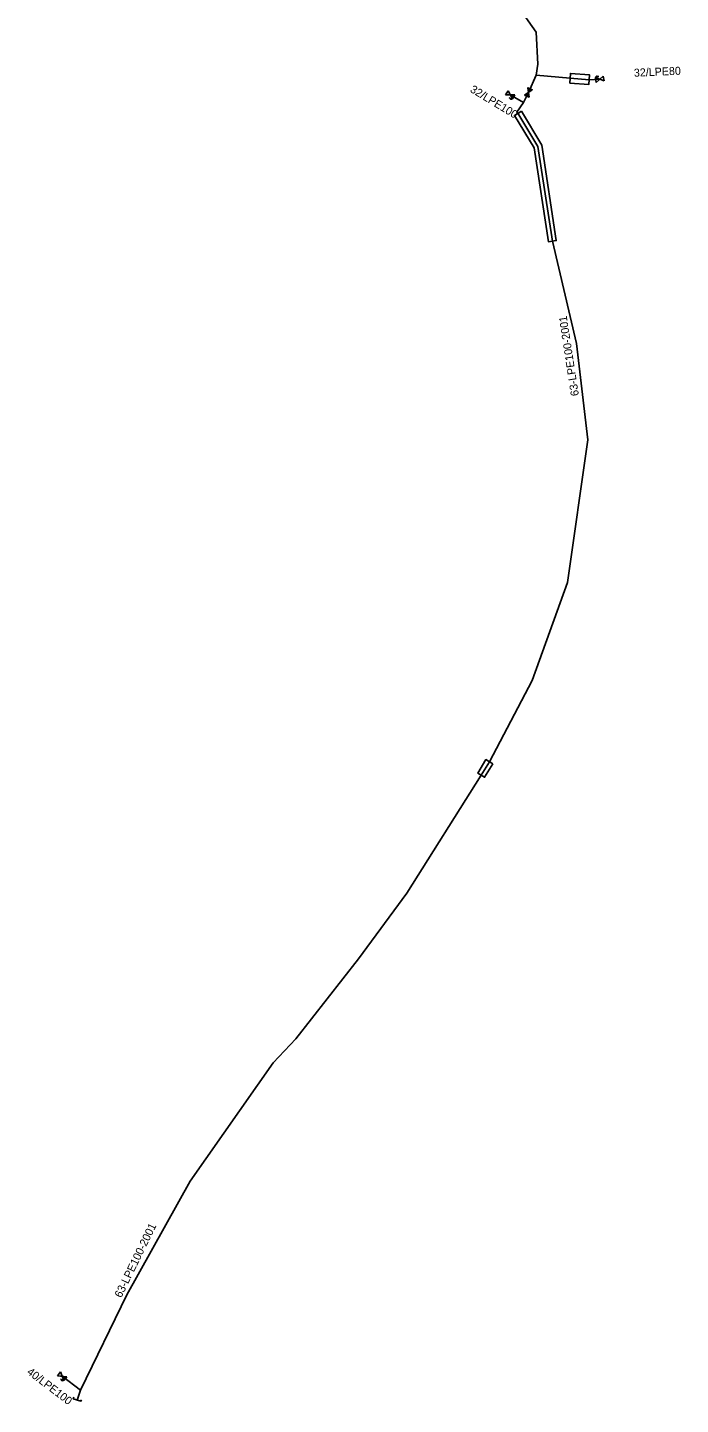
# Model space of a CAD drawing. Extents: x -787723 to -786204, y -1153846 to -1152384.
# Drawn here: x -786628.8 to -786547.2, y -1153807.1 to -1153635 of the extents above; entities that cross this region are included whole.
import ezdxf

# ---------------------------------------------------------------- set-up
doc = ezdxf.new("R2010")
doc.units = 0
for name, color, linetype in [('Vrstva 1', 7, 'Continuous'), ('Vrstva 21', 7, 'Continuous'), ('Vrstva 22', 7, 'Continuous'), ('Vrstva 29', 7, 'Continuous'), ('Vrstva 31', 7, 'Continuous'), ('Vrstva 32', 7, 'Continuous')]:
    doc.layers.add(name, color=color, linetype=linetype)

# ---------------------------------------------------------------- blocks, each defined once
blk = doc.blocks.new('DEC063-SN')
at = {"layer": 'Vrstva 1'}
for p, q in [((-0.5, -0.3), (0.5, 0.3)), ((0.5, -0.3), (-0.5, 0.3)), ((-0.5, 0.3), (-0.5, -0.3)), ((0.5, 0.3), (0.5, -0.3)), ((0.126, -0.318), (0.126, -0.458)), ((0.126, -0.384), (0.206, -0.384)), ((0.206, -0.458), (0.206, -0.318)), ((0.366, -0.458), (0.366, -0.318))]:
    blk.add_line(p, q, dxfattribs=at)
for points in [[(0.246, -0.318), (0.246, -0.418), (0.252, -0.438), (0.264, -0.451), (0.281, -0.458), (0.292, -0.458), (0.309, -0.451), (0.321, -0.438), (0.326, -0.418), (0.326, -0.318)], [(0.366, -0.318), (0.418, -0.318), (0.435, -0.325), (0.441, -0.331), (0.446, -0.344), (0.446, -0.364), (0.441, -0.378), (0.435, -0.384), (0.418, -0.391), (0.366, -0.391)]]:
    blk.add_lwpolyline(points, dxfattribs=at)
blk = doc.blocks.new('DEC130')
at = {"layer": 'Vrstva 1'}
blk.add_lwpolyline([(0.2, 0.5), (0, 0.5), (0, -0.5), (0.2, -0.5)], dxfattribs=at)
blk = doc.blocks.new('DEC124')
at = {"layer": 'Vrstva 1'}
blk.add_lwpolyline([(-0.5, 0.3), (0.5, -0.3), (0.5, 0.3), (-0.5, -0.3), (-0.5, 0.3)], dxfattribs=at)

msp = doc.modelspace()

# ---------------------------------------------------------------- linework, layer by layer
at = {"layer": 'Vrstva 21'}
for points in [[(-786567.51, -1153632.31), (-786565.2, -1153635.57), (-786565, -1153639.57), (-786565.22, -1153640.95), (-786566.18, -1153643.1)], [(-786566.18, -1153643.1), (-786566.79, -1153644.36), (-786567.65, -1153645.57), (-786567.5, -1153645.71), (-786565.01, -1153649.85), (-786563.19, -1153661.69), (-786560.19, -1153674.46), (-786558.76, -1153686.53), (-786561.3, -1153704.35), (-786565.7, -1153716.59), (-786571.07, -1153726.74), (-786572.1, -1153728.42), (-786581.4, -1153743.15), (-786587.43, -1153751.39), (-786595.25, -1153761.37), (-786598.11, -1153764.36), (-786608.48, -1153779.17), (-786616.39, -1153793.35), (-786622.2, -1153805.28), (-786622.61, -1153806.5)]]:
    msp.add_lwpolyline(points, dxfattribs=at)
at = {"layer": 'Vrstva 29'}
for points in [[(-786561.03, -1153641.93), (-786560.93, -1153640.73), (-786558.54, -1153640.92), (-786558.64, -1153642.12)], [(-786567.07, -1153645.45), (-786564.53, -1153649.68), (-786562.7, -1153661.61), (-786563.68, -1153661.77), (-786565.49, -1153650.02), (-786567.93, -1153645.97)], [(-786570.64, -1153727), (-786571.67, -1153728.68), (-786572.53, -1153728.16), (-786571.5, -1153726.48)]]:
    msp.add_lwpolyline(points, close=True, dxfattribs=at)
at = {"layer": 'Vrstva 31'}
for points in [[(-786565.22, -1153640.95), (-786560.98, -1153641.33), (-786558.59, -1153641.52), (-786557.27, -1153641.46)], [(-786566.79, -1153644.36), (-786568.45, -1153643.41)], [(-786622.2, -1153805.28), (-786624.48, -1153803.54)]]:
    msp.add_lwpolyline(points, dxfattribs=at)

# ---------------------------------------------------------------- block references
at = {"layer": 'Vrstva 22'}
for name, p, rotation in [('DEC124', (-786566.18, -1153643.1), 65.93868333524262), ('DEC130', (-786622.61, -1153806.5), 71.42427559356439)]:
    msp.add_blockref(name, p, dxfattribs=dict(at, rotation=rotation))
at = {"layer": 'Vrstva 32'}
for p, rotation in [((-786557.27, -1153641.46), -169.94021674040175), ((-786568.45, -1153643.41), -29.782038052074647), ((-786624.48, -1153803.54), -37.349349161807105)]:
    msp.add_blockref('DEC063-SN', p, dxfattribs=dict(at, rotation=rotation))

# ---------------------------------------------------------------- texts
at = {"layer": 'Vrstva 21'}
for rotation, p in [(98.739, (-786559.87, -1153680.96)), (64.034, (-786617.09, -1153793.8))]:
    msp.add_text('63-LPE100-2001', height=1, rotation=rotation, dxfattribs=at).set_placement(p)
at = {"layer": 'Vrstva 31'}
for s, rotation, p in [('32/LPE80', 2.603, (-786552.98, -1153641.15)), ('32/LPE100', 328.853, (-786573.57, -1153642.98)), ('40/LPE100', 322.651, (-786628.97, -1153803.16))]:
    msp.add_text(s, height=1, rotation=rotation, dxfattribs=at).set_placement(p)

doc.saveas('drawing.dxf')
